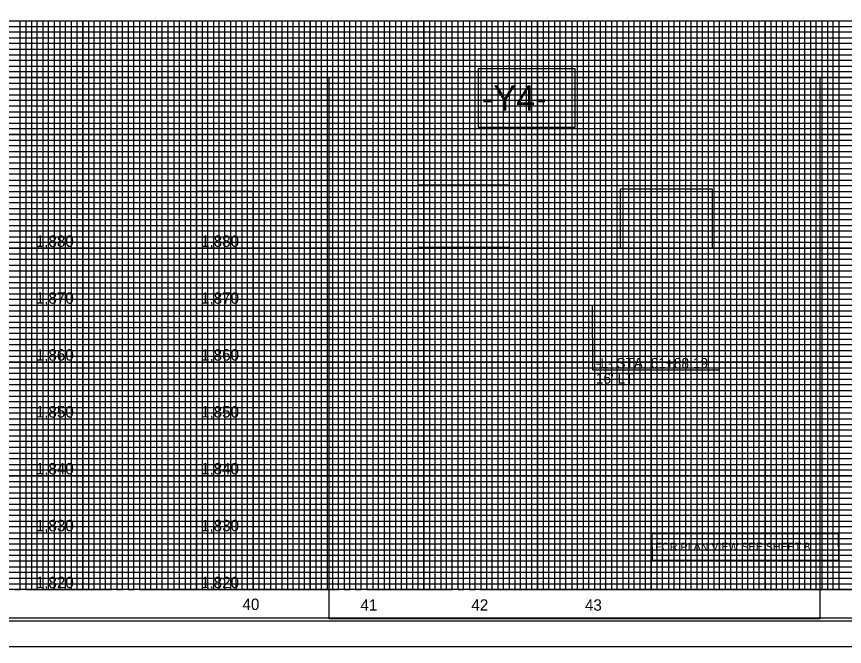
# Model space of a CAD drawing. Extents: x 557032 to 558840, y 515971 to 517218.
# Drawn here: x 557641 to 558369, y 516118 to 516672 of the extents above; entities that cross this region are included whole.
import ezdxf

# ---------------------------------------------------------------- set-up
doc = ezdxf.new("R2010")
doc.units = 0
for name, color, linetype in [('Exist Vertical Profile Horizontal Axis Label Major', 7, 'Continuous'), ('Exist Vertical Profile Vertical Axis Label', 7, 'Continuous'), ('Prop Dimension', 7, 'Continuous'), ('Prop Vertical Profile Curve Label', 7, 'Continuous'), ('Prop Vertical Profile Grade Label', 7, 'Continuous'), ('Prop VPI Label', 7, 'Continuous'), ('Scratch_Level_5', 7, 'Continuous'), ('Sheet Cutting Line CELL', 7, 'Continuous'), ('Sheet DOT Grid CELL', 7, 'Continuous'), ('Sheet Layout Profile Border Port 2', 7, 'Continuous'), ('Sheet Plot Border Inside CELL', 7, 'Continuous'), ('Sheet Plot Border Outside CELL', 7, 'Continuous'), ('Sheet Profile CELL', 7, 'Continuous'), ('Sheet Profile Grid Major CELL', 7, 'Continuous'), ('Sheet Profile Grid Middle CELL', 7, 'Continuous'), ('Sheet Profile Grid Minor CELL', 7, 'Continuous')]:
    doc.layers.add(name, color=color, linetype=linetype)

msp = doc.modelspace()

# ---------------------------------------------------------------- linework, layer by layer
at = {"layer": 'Prop Dimension'}
for points in [[(557649.45, 516168.17), (557699.45, 516168.17), (557699.45, 516518.17), (557649.45, 516518.17)], [(557649.45, 516168.17), (557699.45, 516168.17), (557699.45, 516518.17), (557649.45, 516518.17)], [(557799.45, 516518.17), (557849.45, 516518.17), (557849.45, 516168.17), (557799.45, 516168.17)], [(557799.45, 516518.17), (557849.45, 516518.17), (557849.45, 516168.17), (557799.45, 516168.17)]]:
    msp.add_lwpolyline(points, close=True, dxfattribs=at)
at = {"layer": 'Prop Vertical Profile Curve Label'}
msp.add_lwpolyline([(558047.52, 516626.3), (558132.11, 516626.3), (558132.11, 516574.35), (558047.52, 516574.35)], close=True, dxfattribs=at)
at = {"layer": 'Prop Vertical Profile Grade Label'}
for points in [[(558047.52, 516626.3), (558132.11, 516626.3), (558132.11, 516574.35), (558047.52, 516574.35)], [(557994.43, 516523.96), (558074.45, 516523.96), (558074.45, 516468.82), (557994.43, 516468.82)], [(558172.33, 516520.31), (558252.95, 516520.31), (558252.95, 516468.33), (558172.33, 516468.33)]]:
    msp.add_lwpolyline(points, close=True, dxfattribs=at)
at = {"layer": 'Prop VPI Label'}
for p, q in [((558147.94, 516360.97), (558147.89, 516418.02)), ((558258.91, 516360.97), (558147.94, 516360.97))]:
    msp.add_line(p, q, dxfattribs=at)
for points in [[(558047.52, 516626.3), (558132.11, 516626.3), (558132.11, 516574.35), (558047.52, 516574.35)], [(558200.14, 516217.52), (558363.84, 516217.52), (558364.16, 516193.74), (558200.46, 516193.74)], [(558200.14, 516217.52), (558364.16, 516217.52), (558364.16, 516193.74), (558200.14, 516193.74)]]:
    msp.add_lwpolyline(points, close=True, dxfattribs=at)
at = {"layer": 'Scratch_Level_5'}
for points in [[(558347.74, 516142.47), (557916.16, 516142.47), (557916.16, 516618.58), (558347.74, 516618.58)], [(558074.45, 516168.17), (558699.34, 516168.17), (558699.34, 516568.17), (558074.45, 516568.17)]]:
    msp.add_lwpolyline(points, close=True, dxfattribs=at)
at = {"layer": 'Sheet Cutting Line CELL'}
msp.add_line((557032.45, 516118.17), (558716.45, 516118.17), dxfattribs=at)
at = {"layer": 'Sheet DOT Grid CELL'}
for p, q in [((557199.45, 516668.17), (558699.34, 516668.17)), ((557649.45, 516668.17), (557649.45, 516168.17)), ((557649.45, 516668.17), (557649.45, 516168.17)), ((557699.45, 516668.17), (557699.45, 516168.17)), ((557749.45, 516668.17), (557749.45, 516168.17)), ((557799.45, 516668.17), (557799.45, 516168.17)), ((557849.45, 516668.17), (557849.45, 516168.17)), ((557899.45, 516668.17), (557899.45, 516168.17)), ((557949.45, 516668.17), (557949.45, 516168.17)), ((557999.45, 516668.17), (557999.45, 516168.17)), ((558049.45, 516668.17), (558049.45, 516168.17)), ((558099.45, 516668.17), (558099.45, 516168.17)), ((558149.45, 516668.17), (558149.45, 516168.17)), ((558199.45, 516668.17), (558199.45, 516168.17)), ((558249.45, 516668.17), (558249.45, 516168.17)), ((558299.45, 516668.17), (558299.45, 516168.17)), ((558349.45, 516668.17), (558349.45, 516168.17)), ((557199.45, 516618.17), (558699.34, 516618.17)), ((557199.45, 516568.17), (558699.34, 516568.17)), ((557199.45, 516518.17), (558699.34, 516518.17)), ((557199.45, 516468.17), (558699.34, 516468.17)), ((557199.45, 516418.17), (558699.34, 516418.17)), ((557199.45, 516368.17), (558699.34, 516368.17)), ((557199.45, 516318.17), (558699.34, 516318.17)), ((557199.45, 516268.17), (558699.34, 516268.17)), ((557199.45, 516218.17), (558699.34, 516218.17))]:
    msp.add_line(p, q, dxfattribs=at)
at = {"layer": 'Sheet Layout Profile Border Port 2'}
msp.add_lwpolyline([(557249.45, 516668.17), (558649.45, 516668.17), (558649.45, 516168.17), (557249.45, 516168.17)], close=True, dxfattribs=at)
at = {"layer": 'Sheet Plot Border Inside CELL'}
msp.add_lwpolyline([(557045.45, 516140.62), (558711.95, 516140.62), (558711.95, 517195.72), (557045.45, 517195.72)], close=True, dxfattribs=at)
at = {"layer": 'Sheet Plot Border Outside CELL'}
msp.add_lwpolyline([(557032.45, 516118.17), (558716.45, 516118.17), (558716.45, 517218.17), (557032.45, 517218.17)], close=True, dxfattribs=at)
at = {"layer": 'Sheet Profile CELL'}
for p, q in [((557199.45, 516668.17), (558699.45, 516668.17)), ((558699.45, 516168.17), (557199.45, 516168.17)), ((557199.45, 516143.17), (558699.45, 516143.17))]:
    msp.add_line(p, q, dxfattribs=at)
msp.add_lwpolyline([(558699.45, 517193.17), (557199.45, 517193.17), (557199.45, 516143.17), (558699.45, 516143.17)], close=True, dxfattribs=at)
at = {"layer": 'Sheet Profile Grid Major CELL'}
for p, q in [((557699.45, 516668.17), (557749.45, 516668.17)), ((557799.45, 516668.17), (557849.45, 516668.17)), ((557899.45, 516668.17), (557949.45, 516668.17)), ((557999.45, 516668.17), (558049.45, 516668.17)), ((558099.45, 516668.17), (558149.45, 516668.17)), ((558199.45, 516668.17), (558249.45, 516668.17)), ((558299.45, 516668.17), (558349.45, 516668.17)), ((557699.45, 516468.17), (557699.45, 516518.17)), ((557649.45, 516468.17), (557699.45, 516468.17)), ((557799.45, 516468.17), (557849.45, 516468.17)), ((557649.45, 516418.17), (557699.45, 516418.17)), ((557799.45, 516418.17), (557849.45, 516418.17)), ((557649.45, 516368.17), (557699.45, 516368.17)), ((557799.45, 516368.17), (557849.45, 516368.17)), ((557649.45, 516318.17), (557699.45, 516318.17)), ((557799.45, 516318.17), (557849.45, 516318.17)), ((557649.45, 516268.17), (557649.45, 516268.17)), ((557649.45, 516268.17), (557699.45, 516268.17)), ((557699.45, 516268.17), (557694.45, 516268.17)), ((557799.45, 516268.17), (557849.45, 516268.17)), ((557649.45, 516218.17), (557699.45, 516218.17)), ((557799.45, 516218.17), (557849.45, 516218.17))]:
    msp.add_line(p, q, dxfattribs=at)
for points in [[(557599.45, 516668.17), (557649.45, 516668.17), (557649.45, 516168.17), (557699.45, 516168.17), (557699.45, 516668.17), (557749.45, 516668.17), (557749.45, 516168.17), (557799.45, 516168.17), (557799.45, 516668.17), (557849.45, 516668.17), (557849.45, 516168.17), (557899.45, 516168.17), (557899.45, 516668.17), (557949.45, 516668.17), (557949.45, 516168.17), (557999.45, 516168.17), (557999.45, 516668.17), (558049.45, 516668.17), (558049.45, 516168.17), (558099.45, 516168.17), (558099.45, 516668.17), (558149.45, 516668.17), (558149.45, 516168.17), (558199.45, 516168.17), (558199.45, 516668.17), (558249.45, 516668.17), (558249.45, 516168.17), (558299.45, 516168.17), (558299.45, 516668.17), (558349.45, 516668.17), (558349.45, 516168.17), (558399.45, 516168.17)], [(558699.45, 516618.17), (557199.45, 516618.17)], [(558699.45, 516568.17), (557199.45, 516568.17), (557199.45, 516518.17), (558699.45, 516518.17)], [(558699.45, 516468.17), (557199.45, 516468.17), (557199.45, 516418.17), (558699.45, 516418.17)], [(558699.45, 516368.17), (557199.45, 516368.17), (557199.45, 516318.17), (558699.45, 516318.17)], [(558559.12, 516268.17), (557199.45, 516268.17), (557199.45, 516268.17), (557199.45, 516218.17), (558699.45, 516218.17)], [(558699.45, 516168.17), (557199.45, 516168.17)]]:
    msp.add_lwpolyline(points, dxfattribs=at)
for points in [[(557649.45, 516168.17), (557699.45, 516168.17), (557699.45, 516518.17), (557649.45, 516518.17)], [(557799.45, 516168.17), (557849.45, 516168.17), (557849.45, 516518.17), (557799.45, 516518.17)]]:
    msp.add_lwpolyline(points, close=True, dxfattribs=at)
at = {"layer": 'Sheet Profile Grid Middle CELL'}
for p, q in [((557624.45, 516668.17), (557674.45, 516668.17)), ((557674.45, 516668.17), (557674.45, 516168.17)), ((557724.45, 516168.17), (557724.45, 516668.17)), ((557724.45, 516668.17), (557774.45, 516668.17)), ((557774.45, 516668.17), (557774.45, 516168.17)), ((557824.45, 516168.17), (557824.45, 516668.17)), ((557824.45, 516668.17), (557874.45, 516668.17)), ((557874.45, 516668.17), (557874.45, 516168.17)), ((557924.45, 516168.17), (557924.45, 516668.17)), ((557924.45, 516668.17), (557974.45, 516668.17)), ((557974.45, 516668.17), (557974.45, 516168.17)), ((558024.45, 516168.17), (558024.45, 516668.17)), ((558024.45, 516668.17), (558074.45, 516668.17)), ((558074.45, 516668.17), (558074.45, 516168.17)), ((558124.45, 516168.17), (558124.45, 516668.17)), ((558124.45, 516668.17), (558174.45, 516668.17)), ((558174.45, 516668.17), (558174.45, 516168.17)), ((558224.45, 516168.17), (558224.45, 516668.17)), ((558224.45, 516668.17), (558274.45, 516668.17)), ((558274.45, 516668.17), (558274.45, 516168.17)), ((558324.45, 516168.17), (558324.45, 516668.17)), ((558324.45, 516668.17), (558374.45, 516668.17)), ((557674.45, 516168.17), (557724.45, 516168.17)), ((557774.45, 516168.17), (557824.45, 516168.17)), ((557824.45, 516168.17), (557824.45, 516168.17)), ((557874.45, 516168.17), (557924.45, 516168.17)), ((557974.45, 516168.17), (558024.45, 516168.17)), ((558074.45, 516168.17), (558124.45, 516168.17)), ((558174.45, 516168.17), (558224.45, 516168.17)), ((558274.45, 516168.17), (558324.45, 516168.17))]:
    msp.add_line(p, q, dxfattribs=at)
for points in [[(557199.45, 516643.17), (558699.45, 516643.17)], [(558699.45, 516593.17), (557199.45, 516593.17), (557199.45, 516543.17), (558699.45, 516543.17)], [(558699.45, 516493.17), (557199.45, 516493.17), (557199.45, 516443.17), (558699.45, 516443.17)], [(558699.45, 516393.17), (557199.45, 516393.17), (557199.45, 516343.17), (558699.45, 516343.17)], [(558699.45, 516293.17), (557199.45, 516293.17), (557199.45, 516243.17), (558699.45, 516243.17)], [(558699.45, 516193.17), (557199.45, 516193.17)]]:
    msp.add_lwpolyline(points, dxfattribs=at)
at = {"layer": 'Sheet Profile Grid Minor CELL'}
for p, q in [((557644.45, 516168.17), (557644.45, 516668.17)), ((557644.45, 516668.17), (557654.45, 516668.17)), ((557654.45, 516668.17), (557654.45, 516168.17)), ((557659.45, 516168.17), (557659.45, 516668.17)), ((557659.45, 516668.17), (557664.45, 516668.17)), ((557664.45, 516668.17), (557664.45, 516168.17)), ((557669.45, 516168.17), (557669.45, 516668.17)), ((557669.45, 516668.17), (557679.45, 516668.17)), ((557679.45, 516668.17), (557679.45, 516168.17)), ((557684.45, 516168.17), (557684.45, 516668.17)), ((557684.45, 516668.17), (557689.45, 516668.17)), ((557689.45, 516668.17), (557689.45, 516168.17)), ((557694.45, 516168.17), (557694.45, 516668.17)), ((557694.45, 516668.17), (557704.45, 516668.17)), ((557704.45, 516668.17), (557704.45, 516168.17)), ((557709.45, 516168.17), (557709.45, 516668.17)), ((557709.45, 516668.17), (557714.45, 516668.17)), ((557714.45, 516668.17), (557714.45, 516168.17)), ((557719.45, 516168.17), (557719.45, 516668.17)), ((557719.45, 516668.17), (557729.45, 516668.17)), ((557729.45, 516668.17), (557729.45, 516168.17)), ((557734.45, 516168.17), (557734.45, 516668.17)), ((557734.45, 516668.17), (557739.45, 516668.17)), ((557739.45, 516668.17), (557739.45, 516168.17)), ((557744.45, 516168.17), (557744.45, 516668.17)), ((557744.45, 516668.17), (557754.45, 516668.17)), ((557754.45, 516668.17), (557754.45, 516168.17)), ((557759.45, 516168.17), (557759.45, 516668.17)), ((557759.45, 516668.17), (557764.45, 516668.17)), ((557764.45, 516668.17), (557764.45, 516168.17)), ((557769.45, 516168.17), (557769.45, 516668.17)), ((557769.45, 516668.17), (557779.45, 516668.17)), ((557249.45, 516663.17), (558649.45, 516663.17)), ((558649.45, 516658.17), (557249.45, 516658.17)), ((557249.45, 516653.17), (558649.45, 516653.17)), ((558649.45, 516648.17), (557249.45, 516648.17)), ((557249.45, 516638.17), (558649.45, 516638.17)), ((558649.45, 516633.17), (557249.45, 516633.17)), ((557249.45, 516628.17), (558649.45, 516628.17)), ((558649.45, 516623.17), (557249.45, 516623.17)), ((557249.45, 516613.17), (558649.45, 516613.17)), ((558649.45, 516608.17), (557249.45, 516608.17)), ((557249.45, 516603.17), (558649.45, 516603.17)), ((558649.45, 516598.17), (557249.45, 516598.17)), ((557249.45, 516588.17), (558649.45, 516588.17)), ((558649.45, 516583.17), (557249.45, 516583.17)), ((557249.45, 516578.17), (558649.45, 516578.17)), ((558649.45, 516573.17), (557249.45, 516573.17)), ((557249.45, 516563.17), (558649.45, 516563.17)), ((558649.45, 516558.17), (557249.45, 516558.17)), ((557249.45, 516553.17), (558649.45, 516553.17)), ((558649.45, 516548.17), (557249.45, 516548.17)), ((557249.45, 516538.17), (558649.45, 516538.17)), ((558649.45, 516533.17), (557249.45, 516533.17)), ((557249.45, 516528.17), (558649.45, 516528.17)), ((558649.45, 516523.17), (557249.45, 516523.17)), ((557249.45, 516513.17), (558649.45, 516513.17)), ((558649.45, 516508.17), (557249.45, 516508.17)), ((557249.45, 516503.17), (558649.45, 516503.17)), ((558649.45, 516498.17), (557249.45, 516498.17)), ((557249.45, 516488.17), (558649.45, 516488.17)), ((558649.45, 516483.17), (557249.45, 516483.17)), ((557249.45, 516478.17), (558649.45, 516478.17)), ((558649.45, 516473.17), (557249.45, 516473.32)), ((557249.45, 516463.17), (558649.45, 516463.17)), ((558649.45, 516458.17), (557249.45, 516458.17)), ((557249.45, 516453.17), (558649.45, 516453.17)), ((558649.45, 516448.17), (557249.45, 516448.17)), ((557249.45, 516438.17), (558649.45, 516438.17)), ((558649.45, 516433.17), (557249.45, 516433.17)), ((557249.45, 516428.17), (558649.45, 516428.17)), ((558649.45, 516423.17), (557249.45, 516423.17)), ((557249.45, 516413.17), (558649.45, 516413.17)), ((558649.45, 516408.17), (557249.45, 516408.17)), ((557249.45, 516403.17), (558649.45, 516403.17)), ((558649.45, 516398.17), (557249.45, 516398.17)), ((557249.45, 516388.17), (558649.45, 516388.17)), ((558649.45, 516383.17), (557249.45, 516383.17)), ((557249.45, 516378.17), (558649.45, 516378.17)), ((558649.45, 516373.17), (557249.45, 516373.17)), ((557249.45, 516363.17), (558649.45, 516363.17)), ((558649.45, 516358.17), (557249.45, 516358.17)), ((557249.45, 516353.17), (558649.45, 516353.17)), ((558649.45, 516348.17), (557249.45, 516348.17)), ((557249.45, 516338.17), (558649.45, 516338.17)), ((558649.45, 516333.17), (557249.45, 516333.17)), ((557249.45, 516328.17), (558649.45, 516328.17)), ((558649.45, 516323.17), (557249.45, 516323.17)), ((557249.45, 516313.17), (558649.45, 516313.17)), ((558649.45, 516308.17), (557249.45, 516308.17)), ((557249.45, 516303.17), (558649.45, 516303.17)), ((558649.45, 516298.17), (557249.45, 516298.17)), ((557249.45, 516288.17), (558559.12, 516288.17)), ((558559.12, 516283.17), (557249.45, 516283.17)), ((557249.45, 516278.17), (558559.12, 516278.17)), ((558559.12, 516273.17), (557249.45, 516273.17)), ((557249.45, 516263.17), (558649.45, 516263.17)), ((558649.45, 516258.17), (557249.45, 516258.17)), ((557249.45, 516253.17), (558649.45, 516253.17)), ((558649.45, 516248.17), (557249.45, 516248.17)), ((557249.45, 516238.17), (558649.45, 516238.17)), ((558649.45, 516233.17), (557249.45, 516233.17)), ((557249.45, 516228.17), (558649.45, 516228.17)), ((558649.45, 516223.17), (557249.45, 516223.17)), ((557249.45, 516213.17), (558649.45, 516213.17)), ((558649.45, 516208.17), (557249.45, 516208.17)), ((557249.45, 516203.17), (558649.45, 516203.17)), ((558649.45, 516198.17), (557249.45, 516198.17)), ((557249.45, 516188.17), (558649.45, 516188.17)), ((558649.45, 516183.17), (557249.45, 516183.17)), ((557249.45, 516178.17), (558649.45, 516178.17)), ((557249.45, 516173.17), (558649.45, 516173.17)), ((557639.45, 516168.17), (557644.45, 516168.17)), ((557654.45, 516168.17), (557659.45, 516168.17)), ((557664.45, 516168.17), (557669.45, 516168.17)), ((557679.45, 516168.17), (557684.45, 516168.17)), ((557689.45, 516168.17), (557694.45, 516168.17)), ((557704.45, 516168.17), (557709.45, 516168.17)), ((557714.45, 516168.17), (557719.45, 516168.17)), ((557729.45, 516168.17), (557734.45, 516168.17)), ((557739.45, 516168.17), (557744.45, 516168.17)), ((557754.45, 516168.17), (557759.45, 516168.17)), ((557764.45, 516168.17), (557769.45, 516168.17))]:
    msp.add_line(p, q, dxfattribs=at)
for points in [[(557779.45, 516668.17), (557779.45, 516168.17), (557784.45, 516168.17), (557784.45, 516668.17), (557789.45, 516668.17), (557789.45, 516168.17), (557794.45, 516168.17), (557794.45, 516668.17), (557804.45, 516668.17), (557804.45, 516168.17), (557809.45, 516168.17), (557809.45, 516668.17), (557814.45, 516668.17), (557814.45, 516168.17), (557819.45, 516168.17), (557819.45, 516668.17), (557829.45, 516668.17), (557829.45, 516168.17), (557834.45, 516168.17), (557834.45, 516668.17), (557839.45, 516668.17), (557839.45, 516168.17), (557844.45, 516168.17), (557844.45, 516668.17), (557854.45, 516668.17), (557854.45, 516168.17), (557859.45, 516168.17), (557859.45, 516668.17), (557864.45, 516668.17), (557864.45, 516168.17), (557869.45, 516168.17), (557869.45, 516668.17), (557879.45, 516668.17), (557879.45, 516168.17), (557884.45, 516168.17), (557884.45, 516668.17), (557889.45, 516668.17), (557889.45, 516168.17), (557894.45, 516168.17), (557894.45, 516668.17), (557904.45, 516668.17), (557904.45, 516168.17), (557904.45, 516168.17), (557909.45, 516168.17), (557909.45, 516668.17), (557914.45, 516668.17), (557914.45, 516168.17), (557919.45, 516168.17), (557919.45, 516668.17), (557929.45, 516668.17), (557929.45, 516168.17), (557934.45, 516168.17), (557934.45, 516668.17), (557939.45, 516668.17), (557939.45, 516168.17), (557944.45, 516168.17), (557944.45, 516668.17), (557954.45, 516668.17), (557954.45, 516168.17), (557959.45, 516168.17), (557959.45, 516668.17), (557964.45, 516668.17), (557964.45, 516168.17), (557969.45, 516168.17), (557969.45, 516668.17), (557979.45, 516668.17), (557979.45, 516168.17), (557984.45, 516168.17), (557984.45, 516668.17), (557989.45, 516668.17), (557989.45, 516168.17), (557994.45, 516168.17), (557994.45, 516668.17), (558004.45, 516668.17), (558004.45, 516168.17), (558009.45, 516168.17), (558009.45, 516668.17), (558014.45, 516668.17), (558014.45, 516168.17), (558019.45, 516168.17), (558019.45, 516668.17), (558029.45, 516668.17), (558029.45, 516168.17), (558034.45, 516168.17), (558034.45, 516668.17), (558039.45, 516668.17), (558039.45, 516168.17), (558044.45, 516168.17), (558044.45, 516668.17), (558054.45, 516668.17), (558054.45, 516168.17), (558059.15, 516168.72), (558059.45, 516168.17), (558059.45, 516668.17), (558064.45, 516668.17), (558064.45, 516168.17), (558069.45, 516168.17), (558069.45, 516668.17), (558079.45, 516668.17), (558079.45, 516168.17), (558084.45, 516168.17)], [(558084.45, 516168.17), (558084.45, 516668.17), (558089.45, 516668.17), (558089.45, 516168.17), (558094.45, 516168.17), (558094.45, 516668.17), (558104.45, 516668.17), (558104.45, 516168.17), (558109.45, 516168.17), (558109.45, 516668.17), (558114.45, 516668.17), (558114.45, 516168.17), (558119.45, 516168.17), (558119.45, 516668.17), (558129.45, 516668.17), (558129.45, 516168.17), (558134.45, 516168.17), (558134.45, 516668.17), (558139.45, 516668.17), (558139.45, 516168.17), (558144.45, 516168.17), (558144.45, 516668.17), (558154.45, 516668.17), (558154.45, 516168.17), (558159.45, 516168.17), (558159.45, 516668.17), (558164.45, 516668.17), (558164.45, 516168.17), (558169.45, 516168.17), (558169.45, 516668.17), (558179.45, 516668.17), (558179.45, 516168.17), (558184.45, 516168.17), (558184.45, 516668.17), (558189.45, 516668.17), (558189.45, 516168.17), (558194.45, 516168.17), (558194.45, 516668.17), (558204.45, 516668.17), (558204.45, 516168.17), (558209.45, 516168.17), (558209.45, 516668.17), (558214.45, 516668.17), (558214.45, 516168.17), (558219.45, 516168.17), (558219.45, 516668.17), (558229.45, 516668.17), (558229.45, 516168.17), (558234.45, 516168.17), (558234.45, 516668.17), (558239.45, 516668.17), (558239.45, 516168.17), (558244.45, 516168.17), (558244.45, 516668.17), (558254.45, 516668.17), (558254.45, 516168.17), (558259.45, 516168.17), (558259.45, 516668.17), (558264.45, 516668.17), (558264.45, 516168.17), (558269.45, 516168.17), (558269.45, 516668.17), (558279.45, 516668.17), (558279.45, 516168.17), (558284.45, 516168.17), (558284.45, 516668.17), (558289.45, 516668.17), (558289.45, 516168.17), (558294.45, 516168.17), (558294.45, 516668.17), (558304.45, 516668.17), (558304.45, 516168.17), (558309.45, 516168.17), (558309.45, 516668.17), (558314.45, 516668.17), (558314.45, 516168.17), (558319.45, 516168.17), (558319.45, 516668.17), (558329.45, 516668.17), (558329.45, 516168.17), (558334.45, 516168.17), (558334.45, 516668.17), (558339.45, 516668.17), (558339.45, 516168.17), (558344.45, 516168.17), (558344.45, 516668.17), (558354.45, 516668.17), (558354.45, 516168.17), (558359.45, 516168.17), (558359.45, 516668.17), (558364.45, 516668.17), (558364.45, 516168.17), (558369.45, 516168.17)]]:
    msp.add_lwpolyline(points, dxfattribs=at)

# ---------------------------------------------------------------- texts
at = {"layer": 'Exist Vertical Profile Horizontal Axis Label Major'}
for s, p in [('40', (557839.94, 516150.19)), ('41', (557943.67, 516149.56)), ('42', (558041.19, 516149.56)), ('43', (558141.11, 516149.56))]:
    msp.add_text(s, height=10, dxfattribs=at).set_placement(p)
at = {"layer": 'Exist Vertical Profile Vertical Axis Label'}
for s, p in [('1,880', (557658.15, 516469.42)), ('1,880', (557803.48, 516469.42)), ('1,870', (557658.15, 516419.42)), ('1,870', (557803.48, 516419.42)), ('1,860', (557658.15, 516369.42)), ('1,860', (557803.48, 516369.42)), ('1,850', (557658.15, 516319.42)), ('1,850', (557803.48, 516319.42)), ('1,840', (557658.15, 516269.42)), ('1,840', (557803.48, 516269.42)), ('1,830', (557658.15, 516219.42)), ('1,830', (557803.48, 516219.42)), ('1,820', (557658.15, 516169.42)), ('1,820', (557803.48, 516169.42))]:
    msp.add_text(s, height=10, dxfattribs=at).set_placement(p)
at = {"layer": 'Prop Vertical Profile Grade Label'}
msp.add_text('-Y4-', height=22.5, dxfattribs=at).set_placement((558050.49, 516588.98))
at = {"layer": 'Prop VPI Label'}
for s, height, p in [('-L- STA. 61+88.19', 9, (558150.72, 516362.75)), ("16' LT", 9, (558150.72, 516349.25)), ('FOR PLAN VIEW SEE SHEET 8', 7, (558202.82, 516202.34))]:
    msp.add_text(s, height=height, dxfattribs=at).set_placement(p)

doc.saveas('drawing.dxf')
